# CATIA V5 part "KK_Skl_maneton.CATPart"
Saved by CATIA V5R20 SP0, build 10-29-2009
Part number: Skl_maneton
Publications: "Axe_pivot_manche_maneton", "Droite.7", "Axe_maneton_biellette", "Point.2", "Plan.Ref3", "Point.3", "Plan_Ref1"
Bounding box of the stored display mesh (mm): x 0 to 20, y 85 to 100, z 0 to 0
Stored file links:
  G:\Khaled_CFAO_2011\ST2M\ST2M_GR2\aandujar\Khaled\CAD_thinkMOTION\KK_Skl_maneton.CATPart
  G:\Khaled_CFAO_2011\ST2M\ST2M_GR2\aandujar\Khaled\CAD_thinkMOTION\KK_Skl_scie_mecanique.CATProduct
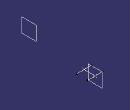
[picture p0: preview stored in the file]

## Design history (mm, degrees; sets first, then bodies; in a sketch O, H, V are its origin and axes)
WSupportSet1: ActiveGrid {3dwsupport RefPoint {point stored without definition}, 3DWOS ({wsupport Support xy-plane, RefPoint {3dwsupport}, GridIn {cartgrid Value 100, Stepbid1 0, Value 100, Stepbid2 0, Direction (1, 0, 0)}, GeometricData ({line type PtDir, Direction (1, 0, 0), Support xy-plane}; {line type PtDir, Direction (0, 1, 0), Support yz-plane})}; {wsupport Support yz-plane, RefPoint {3dwsupport}, GridIn {cartgrid Value 100, Stepbid1 0, Value 100, Stepbid2 0, Direction (0, 1, 0)}, GeometricData ({line type PtDir, Direction (0, 1, 0), Support yz-plane}; {line type PtDir, Direction (0, 0, 1), Support zx-plane})}; {wsupport Support zx-plane, RefPoint {3dwsupport}, GridIn {cartgrid Value 100, Stepbid1 0, Value 100, Stepbid2 0, Direction (0, 0, 1)}, GeometricData ({line type PtDir, Direction (0, 0, 1), Support zx-plane}; {line type PtDir, Direction (1, 0, 0), Support xy-plane})}), GeometricData ({line type PtDir, RefPoint {point stored without definition}, Direction (1, 0, 0), Support xy-plane}; {line type PtDir, RefPoint {point stored without definition}, Direction (0, 1, 0), Support yz-plane}; {line type PtDir, RefPoint {point stored without definition}, Direction (0, 0, 1), Support zx-plane})}
Set1
  Line1 "Axe_pivot_manche_maneton": type Normal, RefPoint Point1, RefSkin Plane2, Start -10, End 10
  Line2: type PtPt, FirstPoint Point1, SecondPoint Point2
  Line3 "Axe_maneton_biellette": type Normal, RefPoint Point2, RefSkin Plane2, Start -10, End 10
Set2
  Point1: linked copy from another document
  Plane1 "Plan.Ref3": linked copy from another document
  Point2: linked copy from another document
  Plane2 "Plan_Ref1": linked copy from another document
Body1 (main body)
